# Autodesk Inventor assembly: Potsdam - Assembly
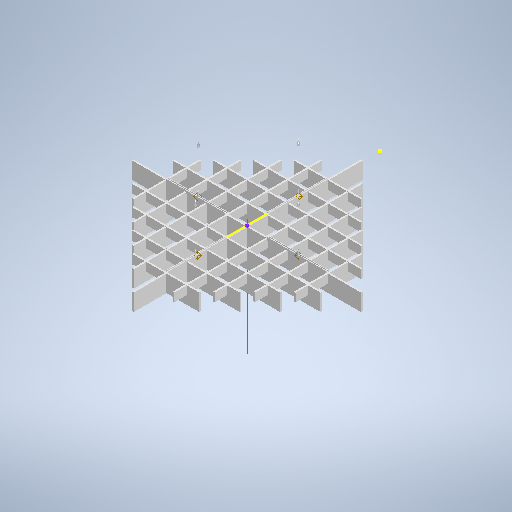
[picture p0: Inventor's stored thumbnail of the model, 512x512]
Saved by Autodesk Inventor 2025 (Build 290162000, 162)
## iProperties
Created: 2024-06
Part Number: Potsdam - Assembly
Document SubType Name: Assembly
Designer: GeorgeBrown
Author: GeorgeBrown
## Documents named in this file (9)
- C:\Users\GeorgeBrown\Synergy commercial Lighting\Synergy Shared - Public\Synergy\Synergy Drawings\S0079 - Potsdam Acoustic Baffle\Design\General Assemblies\Potsdam 1200 x 1200\Potsdam - 1200x1200 Assembly.iam
- C:\Users\GeorgeBrown\Synergy commercial Lighting\Synergy Shared - Public\Synergy\Synergy Drawings\S0079 - Potsdam Acoustic Baffle\Design\Parts\S0079_1200x1200\Inventor\Parts\Potsdam - Part 2.ipt
- C:\Users\GeorgeBrown\Synergy commercial Lighting\Synergy Shared - Public\Synergy\Synergy Drawings\S0079 - Potsdam Acoustic Baffle\Design\Parts\S0079_1200x1200\Inventor\Parts\Potsdam - Part 1.ipt
- C:\Users\GeorgeBrown\Synergy commercial Lighting\Synergy Shared - Public\Synergy\Synergy Drawings\S0079 - Potsdam Acoustic Baffle\Design\Parts\S0079_1200x1200\Inventor\Parts\Potsdam - Part 6.ipt
- C:\Users\GeorgeBrown\Synergy commercial Lighting\Synergy Shared - Public\Synergy\Synergy Drawings\S0079 - Potsdam Acoustic Baffle\Design\Parts\S0079_1200x1200\Inventor\Parts\Potsdam - Part 3.ipt
- C:\Users\GeorgeBrown\Synergy commercial Lighting\Synergy Shared - Public\Synergy\Synergy Drawings\S0079 - Potsdam Acoustic Baffle\Design\Parts\S0079_1200x1200\Inventor\Parts\Potsdam - Part 4.ipt
- C:\Users\GeorgeBrown\Synergy commercial Lighting\Synergy Shared - Public\Synergy\Synergy Drawings\S0079 - Potsdam Acoustic Baffle\Design\Parts\S0079_1200x1200\Inventor\Parts\Potsdam - Part 5.ipt
- C:\Users\GeorgeBrown\Synergy commercial Lighting\Synergy Shared - Public\Synergy\Synergy Drawings\Acoustic ACF parts\12mm Sus rail 0438.ipt
- C:\Users\GeorgeBrown\Synergy commercial Lighting\Synergy Shared - Public\Synergy\Synergy Drawings\F-Code Components\F000264 - 2m suspension kit\F000264 - Wire suspension.iam
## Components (26 placed, 8 different names)
1. Potsdam - Part 2:1
2. Potsdam - Part 1:1
3. Potsdam - Part 3:1 — Mate:60, Mate:61
4. Potsdam - Part 4:1 — Mate:29, Mate:30, Mate:31
5. Potsdam - Part 5:1 — Mate:17, Mate:18, Mate:19
6. Potsdam - Part 6:1 — Mate:7, Mate:8, Mate:9, Mate:10, Mate:36
7. Potsdam - Part 3:2 — Mate:44, Mate:45, Mate:46
8. Potsdam - Part 4:2 — Mate:32, Mate:33, Mate:34
9. Potsdam - Part 5:2 — Mate:20, Mate:21, Mate:22
10. Potsdam - Part 6:2 — Mate:4, Mate:5, Mate:6, Mate:8, Mate:9, Mate:10, Mate:54
11. Potsdam - Part 3:3 — Mate:47, Mate:48, Mate:49
12. Potsdam - Part 4:3 — Mate:35, Mate:36, Mate:37
13. Potsdam - Part 5:3 — Mate:23, Mate:24, Mate:25
14. Potsdam - Part 6:3 — Mate:11, Mate:12, Mate:13, Mate:15, Mate:60, Mate:61
15. Potsdam - Part 3:4 — Mate:50, Mate:51, Mate:52
16. Potsdam - Part 4:4 — Mate:38, Mate:39, Mate:40
17. Potsdam - Part 5:4 — Mate:26, Mate:27, Mate:28
18. Potsdam - Part 6:4 — Mate:14, Mate:15, Mate:16
19. F000264 - Wire suspension:1 [sub-assembly] — Mate:58
20. F000264 - Wire suspension:2 [sub-assembly] — Mate:59
21. F000264 - Wire suspension:3 [sub-assembly] — Mate:57
22. F000264 - Wire suspension:4 [sub-assembly] — Mate:56
23. 12mm Sus rail 0438:1 — Mate:53, Mate:54, Mate:55, Mate:58
24. 12mm Sus rail 0438:2 — Mate:59
25. 12mm Sus rail 0438:3 — Mate:56
26. 12mm Sus rail 0438:4 — Mate:57
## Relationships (55: Mate 55)
- Mate:4: Potsdam - Part 6:2
- Mate:5: Potsdam - Part 6:2
- Mate:6: Potsdam - Part 6:2
- Mate:7: Potsdam - Part 6:1
- Mate:8: Potsdam - Part 6:1 ↔ Potsdam - Part 6:2
- Mate:9: Potsdam - Part 6:1 ↔ Potsdam - Part 6:2
- Mate:10: Potsdam - Part 6:1 ↔ Potsdam - Part 6:2
- Mate:11: Potsdam - Part 6:3
- Mate:12: Potsdam - Part 6:3
- Mate:13: Potsdam - Part 6:3
- Mate:14: Potsdam - Part 6:4
- Mate:15: Potsdam - Part 6:3 ↔ Potsdam - Part 6:4
- Mate:16: Potsdam - Part 6:4
- Mate:17: Potsdam - Part 5:1
- Mate:18: Potsdam - Part 5:1
- Mate:19: Potsdam - Part 5:1
- Mate:20: Potsdam - Part 5:2
- Mate:21: Potsdam - Part 5:2
- Mate:22: Potsdam - Part 5:2
- Mate:23: Potsdam - Part 5:3
- Mate:24: Potsdam - Part 5:3
- Mate:25: Potsdam - Part 5:3
- Mate:26: Potsdam - Part 5:4
- Mate:27: Potsdam - Part 5:4
- Mate:28: Potsdam - Part 5:4
- Mate:29: Potsdam - Part 4:1
- Mate:30: Potsdam - Part 4:1
- Mate:31: Potsdam - Part 4:1
- Mate:32: Potsdam - Part 4:2
- Mate:33: Potsdam - Part 4:2
- Mate:34: Potsdam - Part 4:2
- Mate:35: Potsdam - Part 4:3
- Mate:36: Potsdam - Part 6:1 ↔ Potsdam - Part 4:3
- Mate:37: Potsdam - Part 4:3
- Mate:38: Potsdam - Part 4:4
- Mate:39: Potsdam - Part 4:4
- Mate:40: Potsdam - Part 4:4
- Mate:44: Potsdam - Part 3:2
- Mate:45: Potsdam - Part 3:2
- Mate:46: Potsdam - Part 3:2
- Mate:47: Potsdam - Part 3:3
- Mate:48: Potsdam - Part 3:3
- Mate:49: Potsdam - Part 3:3
- Mate:50: Potsdam - Part 3:4
- Mate:51: Potsdam - Part 3:4
- Mate:52: Potsdam - Part 3:4
- Mate:53: 12mm Sus rail 0438:1
- Mate:54: Potsdam - Part 6:2 ↔ 12mm Sus rail 0438:1
- Mate:55: 12mm Sus rail 0438:1
- Mate:56: F000264 - Wire suspension:4 ↔ 12mm Sus rail 0438:3
- Mate:57: F000264 - Wire suspension:3 ↔ 12mm Sus rail 0438:4
- Mate:58: F000264 - Wire suspension:1 ↔ 12mm Sus rail 0438:1
- Mate:59: F000264 - Wire suspension:2 ↔ 12mm Sus rail 0438:2
- Mate:60: Potsdam - Part 3:1 ↔ Potsdam - Part 6:3
- Mate:61: Potsdam - Part 3:1 ↔ Potsdam - Part 6:3
